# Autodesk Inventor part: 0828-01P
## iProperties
Shininess: 64.0
Length Units: 11269
Angle Units: 11279
Time Units: 11290
Mass Units: 11283
Length Display Precision: 3
Angle Display Precision: 2
Compacted: True
Part Number: 0828-01P
Document SubType Name: Modeling
Created: 2003-08
Designer: 40664
Manufacturer: Standard
Standards Organization: Custom
Density: 0.0
Volumn: 0.0
Area: 0.0
PropertySet Name: Model Information
Control State: 0
Master: False
Checked Out: False
Author: 40664
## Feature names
1. Extrusion1
2. Hole1
